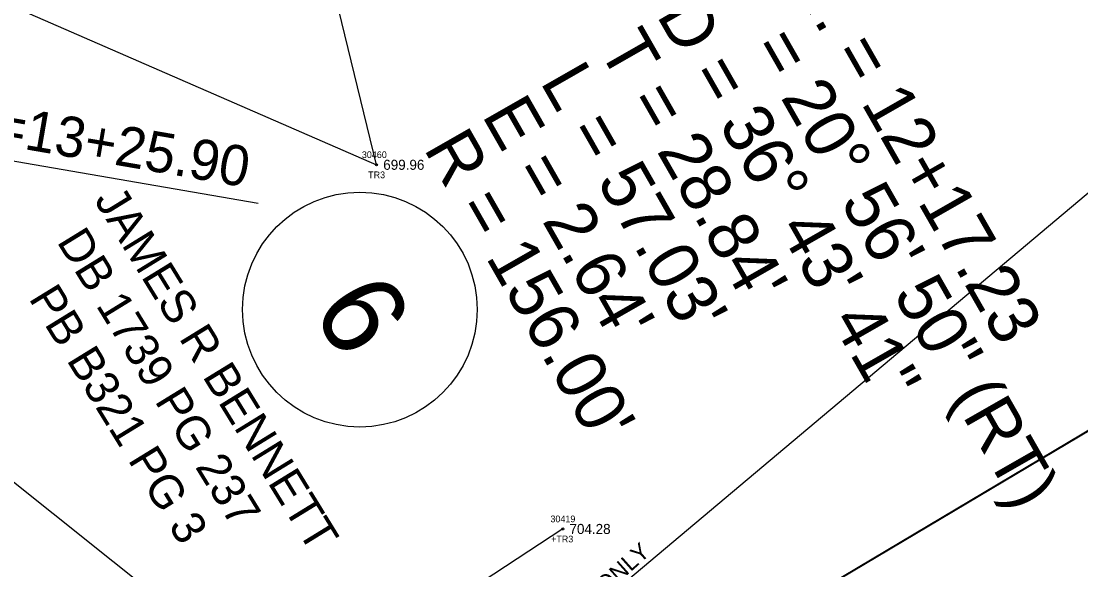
# Model space of a CAD drawing. Extents: x 1375131 to 1378678, y 999028 to 1004053.
# Drawn here: x 1377497.1 to 1377655.1, y 1001508.1 to 1001589.9 of the extents above; entities that cross this region are included whole.
import ezdxf

# ---------------------------------------------------------------- set-up
doc = ezdxf.new("R2010")
doc.units = 0
for name, color, linetype in [('RD_EX_DV_Prop', 7, 'Continuous'), ('RD_EX_DV_TX_Prop(Owner ID)', 7, 'Continuous'), ('RD_EX_SU_Elec', 7, 'Continuous'), ('RD_EX_TX_VEG_ELEV', 7, 'Continuous'), ('RD_EX_VEG', 7, 'Continuous'), ('RD_EX_VEG_txCode', 7, 'Continuous'), ('RD_HC_Data', 7, 'Continuous'), ('RD_SMD_Locator', 7, 'Continuous'), ('RD_TX_Utilities', 7, 'Continuous')]:
    doc.layers.add(name, color=color, linetype=linetype)

msp = doc.modelspace()

# ---------------------------------------------------------------- linework, layer by layer
at = {"layer": 'RD_EX_DV_Prop'}
msp.add_line((1377529.84, 1001453.73), (1377899.3, 1001673.34), dxfattribs=at)
msp.add_lwpolyline([(1377529.29, 1001453.41), (1377714.25, 1001563.46), (1377899.3, 1001673.34), (1377682.07, 1002046.67), (1377670.59, 1002066)], dxfattribs=at)
at = {"layer": 'RD_EX_DV_TX_Prop(Owner ID)'}
msp.add_circle((1377547.59, 1001546.92), 17.5, dxfattribs=at)
at = {"layer": 'RD_EX_SU_Elec'}
msp.add_lwpolyline([(1377317.71, 1001704), (1377525.76, 1001454.69), (1377725.47, 1001622.6)], dxfattribs=at)
at = {"layer": 'RD_EX_VEG'}
msp.add_lwpolyline([(1377577.84, 1001514.22), (1377523.1, 1001478.27), (1377519.66, 1001502.24), (1377466.46, 1001544.71), (1377441.17, 1001585.98), (1377464.76, 1001601.81), (1377468.99, 1001603.82), (1377550.07, 1001568.51), (1377532.63, 1001640.14), (1377553.09, 1001666.26), (1377550.19, 1001700.64), (1377559.94, 1001738.84), (1377584.48, 1001779.7), (1377605.02, 1001797.57)], dxfattribs=at)
at = {"layer": 'RD_HC_Data'}
msp.add_line((1377412.12, 1001583.58), (1377532.41, 1001562.79), dxfattribs=at)
at = {"layer": 'RD_SMD_Locator'}
for centre in [(1377550.07, 1001568.51), (1377577.84, 1001514.22)]:
    msp.add_circle(centre, 0.15, dxfattribs=at)

# ---------------------------------------------------------------- texts
at = {"layer": 'RD_EX_DV_TX_Prop(Owner ID)'}
for s, height, p in [('JAMES R BENNETT', 5, (1377507.88, 1001563.26)), ('DB 1739 PG 237', 5, (1377502.31, 1001557.06)), ('PB B321 PG 3', 5, (1377498.12, 1001548.6)), ('6', 12.5, (1377540.25, 1001546.91))]:
    msp.add_text(s, height=height, rotation=301.5778, dxfattribs=at).set_placement(p)
at = {"layer": 'RD_EX_TX_VEG_ELEV'}
for s, p in [('699.96', (1377551.07, 1001567.76)), ('704.28', (1377578.84, 1001513.47))]:
    msp.add_text(s, height=1.5, dxfattribs=at).set_placement(p)
at = {"layer": 'RD_EX_VEG_txCode'}
for s, p in [('30460', (1377547.88, 1001569.51)), ('TR3', (1377548.82, 1001566.51)), ('30419', (1377576, 1001515.22)), ('+TR3', (1377576.1, 1001512.22))]:
    msp.add_text(s, height=1, dxfattribs=at).set_placement(p)
at = {"layer": 'RD_HC_Data'}
for s, height, rotation, p in [('P.I. = 12+17.23', 7.5, 299.7451, (1377609.11, 1001600.73)), ('D = 36%%d 43\' 41"', 7.5, 299.7451, (1377591.74, 1001590.81)), ("T = 28.84'", 7.5, 299.7451, (1377583.06, 1001585.85)), ('    = 20%%d 56\' 50" (RT)', 7.5, 299.7451, (1377600.42, 1001595.77)), ("L = 57.03'", 7.5, 299.7451, (1377574.38, 1001580.89)), ('POT=13+25.90', 6, 350.1911, (1377476.51, 1001574.48)), ("E = 2.64'", 7.5, 299.7451, (1377565.69, 1001575.92)), ("R = 156.00'", 7.5, 299.7451, (1377557.01, 1001570.96))]:
    msp.add_text(s, height=height, rotation=rotation, dxfattribs=at).set_placement(p)
at = {"layer": 'RD_TX_Utilities'}
msp.add_text('PWR ONLY', height=2.5, rotation=41.7989, dxfattribs=at).set_placement((1377577.71, 1001498.62))

doc.saveas('drawing.dxf')
